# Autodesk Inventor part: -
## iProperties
Shininess: 50.0
Length Units: 11272
Angle Units: 11279
Time Units: 11290
Mass Units: 11286
Length Display Precision: 3
Angle Display Precision: 2
Part Number: -
Document SubType Name: Modeling
Created: 2004-07
Material: AISI 1018/1020
Manufacturer: Standard
Standards Organization: Custom
Designer: CM
Description: 1/4 Countersink Washer
Density: 10.49
Volumn: 2.304646865681294
Area: 8.437628188859923
PropertySet Name: Model Information
Control State: 0
Master: False
Checked Out: False
Author: CM
